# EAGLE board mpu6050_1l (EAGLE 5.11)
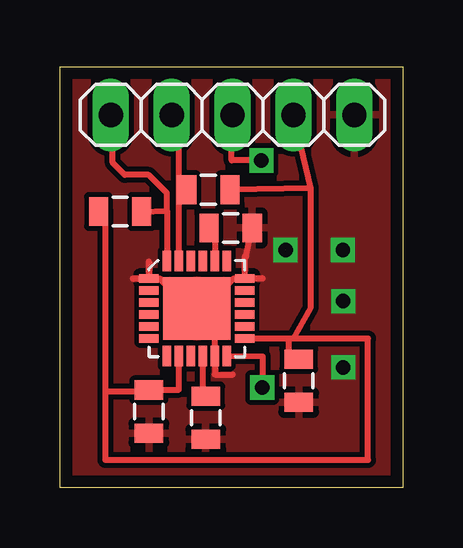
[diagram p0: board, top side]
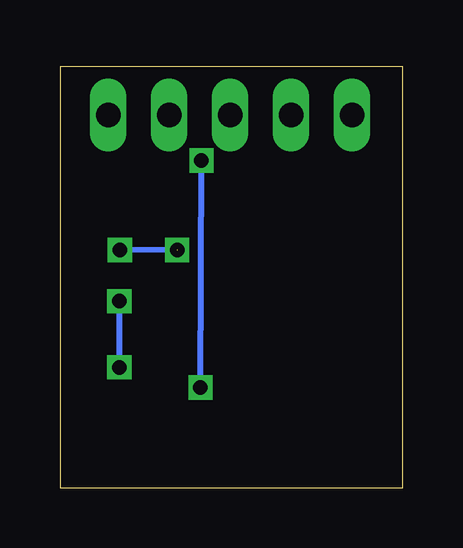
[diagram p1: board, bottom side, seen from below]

Size 14.3 x 17.53 mm. Coordinates in mm from the lower left corner, seen from the top.
Outline: 0,17.53 14.3,17.53 14.3,0 0,0 0,17.53
Copper layers (1*16): Top 0.035mm / dielectric 1.5mm / Bottom 0.035mm
Design rules "default *": minimum track width 10mil, minimum drill 0.4mm, track to track 8mil, track to pad 8mil, pad to pad 8mil, via to via 8mil, smd to smd 8mil, copper to edge 20mil, drill to drill 8mil, minimum pad ring 10mil, minimum via ring 8mil, stop-mask expansion 4mil, vias tented up to drill 0.6mm, thermal gap 10mil

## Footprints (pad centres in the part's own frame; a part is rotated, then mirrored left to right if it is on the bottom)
0805 = smd 0.8 x 1.2: 1 -0.9,0; 2 0.9,0
QFN24 = smd 0.8 x 0.35: 1 -2,1.25; 2 -2,0.75; 3 -2,0.25; 4 -2,-0.25; 5 -2,-0.75; 6 -2,-1.25; 13 2,-1.25; 14 2,-0.75; 15 2,-0.25; 16 2,0.25; 17 2,0.75; 18 2,1.25 | smd 0.35 x 0.85: 7 -1.25,-1.975; 8 -0.75,-1.975; 9 -0.25,-1.975; 10 0.25,-1.975; 11 0.75,-1.975; 12 1.25,-1.975; 19 1.25,1.975; 20 0.75,1.975; 21 0.25,1.975; 22 -0.25,1.975; 23 -0.75,1.975; 24 -1.25,1.975 | smd 2.8 x 2.6: P 0,0
1X05 = drill 1.016 long: 1 -5.08,0; 2 -2.54,0; 3 0,0; 4 2.54,0; 5 5.08,0

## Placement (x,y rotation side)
C1  [0805]  6.08,2.91 90 top
C2  [0805]  3.71,3.17 90 top
C3  [0805]  9.96,4.45 270 top
C4  [0805]  7.12,10.82 0 top
IC1  MPU-6050  [QFN24]  5.71,7.46 0 top
JP1  [1X05]  7.2,15.53 180 top
R1  [0805]  6.19,12.41 0 top
R2  [0805]  2.51,11.5 180 top

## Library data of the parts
C1-C4 R1 R2 = SparkFun
IC1 = seb
JP1 = pinhead-2

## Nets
+3V3: C2.2 C3.1 IC1.8 IC1.13 JP1.2 R1.2 R2.2
GND: C1.1 C2.1 C3.2 C4.2 IC1.1 IC1.11 IC1.18 IC1.P JP1.1
INT: IC1.12 JP1.3
N$2: C1.2 IC1.10
N$3: C4.1 IC1.20
SCL: IC1.23 JP1.4 R1.1
SDA: IC1.24 JP1.5 R2.1

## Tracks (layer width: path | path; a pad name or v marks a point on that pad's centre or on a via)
+3V3
  Top 0.254: IC1.8 4.96,4.08 C2.2 3.2,4.03 3.2,4.01 1.9,4.01 | 10.46,12.48 10.46,7.5 9.74,6.21 | 10.46,12.48 JP1.2 | R2.2 1.9,11.53 1.9,10.23 1.9,5.33 1.9,4.01 | 10.46,12.48 R1.2 | 9.74,6.21 9.54,6.21 | 9.54,6.21 IC1.13 | C3.1 9.54,5.59 9.54,6.21 | 1.9,4.01 1.9,1.15 12.85,1.15 12.85,6.21 9.74,6.21
GND  (via drill 0.6)  (1 unrouted)
  Top 0.254: 3.28,8.7 3.06,8.7 3.04,8.72 | 3.28,8.7 3.45,8.7 | 8.45,8.72 8.44,8.73 7.96,8.73 7.71,8.73 | 7.2,4.71 6.46,4.71 IC1.11 6.46,7.46 IC1.P | IC1.P 6.53,8.28 6.81,8.28 7.24,8.71 IC1.18 7.71,8.73 | IC1.P 5.13,8.04 4.83,8.04 4.16,8.71 IC1.1 3.71,9.41 IC1.1 3.28,8.7 | 7.71,8.73 7.71,9.62 7.77,9.62 C4.2
  Bottom 0.254: v11.82,5.01 v11.82,7.77 | v9.4,9.9 v11.79,9.89
  pour Top: 0,17.53 14.09,17.51 14.19,-0.44 0.1,-0.42
INT  (via drill 0.6)
  Top 0.254: JP1.3 7.16,13.63 v8.4,13.63 | v8.44,4.17 8.45,5.46 IC1.12
  Bottom 0.254: v8.4,13.63 v8.44,4.18 v8.44,4.17
N$2
  Top 0.254: C1.2 5.96,3.98 IC1.10
N$3
  Top 0.254: IC1.20 6.46,10.8 C4.1
S$1
  Top 0.254: 6.5,5.53 6.46,5.53 6.46,6.64
S$2
  Top 0.254: 7.72,8.7 7.24,8.7 6.92,8.38
S$3
  Top 0.254: 3.76,8.69 4.2,8.69 4.51,8.38
SCL
  Top 0.254: IC1.23 4.96,12.23 | 4.96,12.23 R1.1 | JP1.4 4.96,15.53 4.96,12.23
SDA
  Top 0.254: 4.46,11.53 IC1.24 | R2.1 4.46,11.53 | JP1.5 2.2,15.53 2.2,13.53 2.7,13.03 3.7,13.03 4.46,12.27 4.46,11.53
